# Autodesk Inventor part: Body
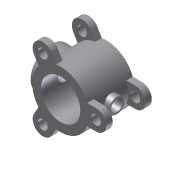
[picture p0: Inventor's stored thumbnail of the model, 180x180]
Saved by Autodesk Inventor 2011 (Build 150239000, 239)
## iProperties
Created: 2009-04
Part Number: Body
Document SubType Name: Modeling
Designer: Sham
Density: 1 g/cm^3
Author: Sham
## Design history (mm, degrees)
sketch "Sketch1"
  geometry: C1 r 97 at (0, 0); C2 r 140 at (0, 0)
  constraints: 2 centre point, 1 coincident
  dimensions: "d2" = 194 diameter of C1; "d3" = 280 diameter of C2
extrude "Extrusion1" new body sketch "Sketch1" distance "d4" = 225; taper "d5" = 0 deg
workplane "Work Plane1"
sketch "Sketch2"
  geometry: L1 (-140, 0)-(140, 0) reference; C1 r 100 at (0, 112.5)
  constraints: 1 centre point
  dimensions: "d7" = 200 diameter of C1; "d8" = 112.5 distance from line of L1 C1.centre
extrude "Extrusion2" join sketch "Sketch2" stored distance "d9" = 225; taper "d10" = 0 deg
hole "Hole4" diameter "d40" = 56; stored, may be unused: countersink angle "d44" = 90 deg, drill point angle "d46" = 118 deg; dims "d38" = 10, "d39" = 10, "d41" = 6, "d42" = 100, "d43" = 25, "d45" = 8
sketch "Sketch3"
  geometry: C1 r 50 at (0, 0) reference; 3 further points
  constraints: 4 other
  dimensions: "d47" = 75 distance of point (75, 0) C1.centre; "d50" = 360 deg dimension on C1.centre point (75, 0) (derived)
hole "Hole5" sketch "Sketch3" at (75, 0), (-37.5, 64.952), (-37.5, -64.952) diameter "d52" = 20.3; stored, may be unused: countersink angle "d56" = 90 deg, drill point angle "d58" = 118 deg; dims "d53" = 6, "d54" = 100, "d55" = 25, "d57" = 15
workplane "Work Plane2"
sketch "Sketch4"
  geometry: L1 (-140, 225)-(140, 225) reference; C1 r 37.5 at (0, 112.5)
  constraints: 1 centre point
  dimensions: "d60" = 75 diameter of C1; "d61" = 112.5 distance from line of L1 C1.centre
extrude "Extrusion3" join sketch "Sketch4" stored distance "d62" = 225; taper "d63" = 0 deg
sketch "Sketch5"
  geometry: C1 r 37.5 at (0, 0) reference; C2 r 28 at (0, 0)
  constraints: 1 centre point, 1 coincident
  dimensions: "d64" = 56 diameter of C2
extrude "Extrusion4" cut sketch "Sketch5" distance "d65" = 225; taper "d66" = 0 deg
sketch "Sketch7"
  geometry: L1 (-130.767, -50)-(-175, -50); L2 (-175, 50)-(-130.767, 50); C1 r 97 at (0, 0) reference; C2 r 23.5 at (-175, 0); A1 r 140 centre (0, 0) between (-130.767, -50) and (-130.767, 50) reference; A2 r 50 centre (-175, 0) between (-175, 50) and (-175, -50)
  constraints: 4 end point, 4 point on circle, 2 centre point, 2 tangent, 1 coincident, 1 horizontal, 1 horizontal alignment, 1 parallel
  dimensions: "d76" = 50 radius of A2; "d77" = 175 distance of C1.centre A2.centre; "d78" = 47 diameter of C2
extrude "Extrusion5" join sketch "Sketch7" distance "d79" = 32; taper "d80" = 0 deg
pattern_circular "Circular Pattern1" dims angle "d82" = 360 deg
workplane "Work Plane3"
mirror "Mirror1"
body "Solid1"
other parameters: "d59" = 325, "d84" = -112.5
